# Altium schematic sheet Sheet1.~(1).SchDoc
size D; SheetNumber: 1; SheetTotal: 1
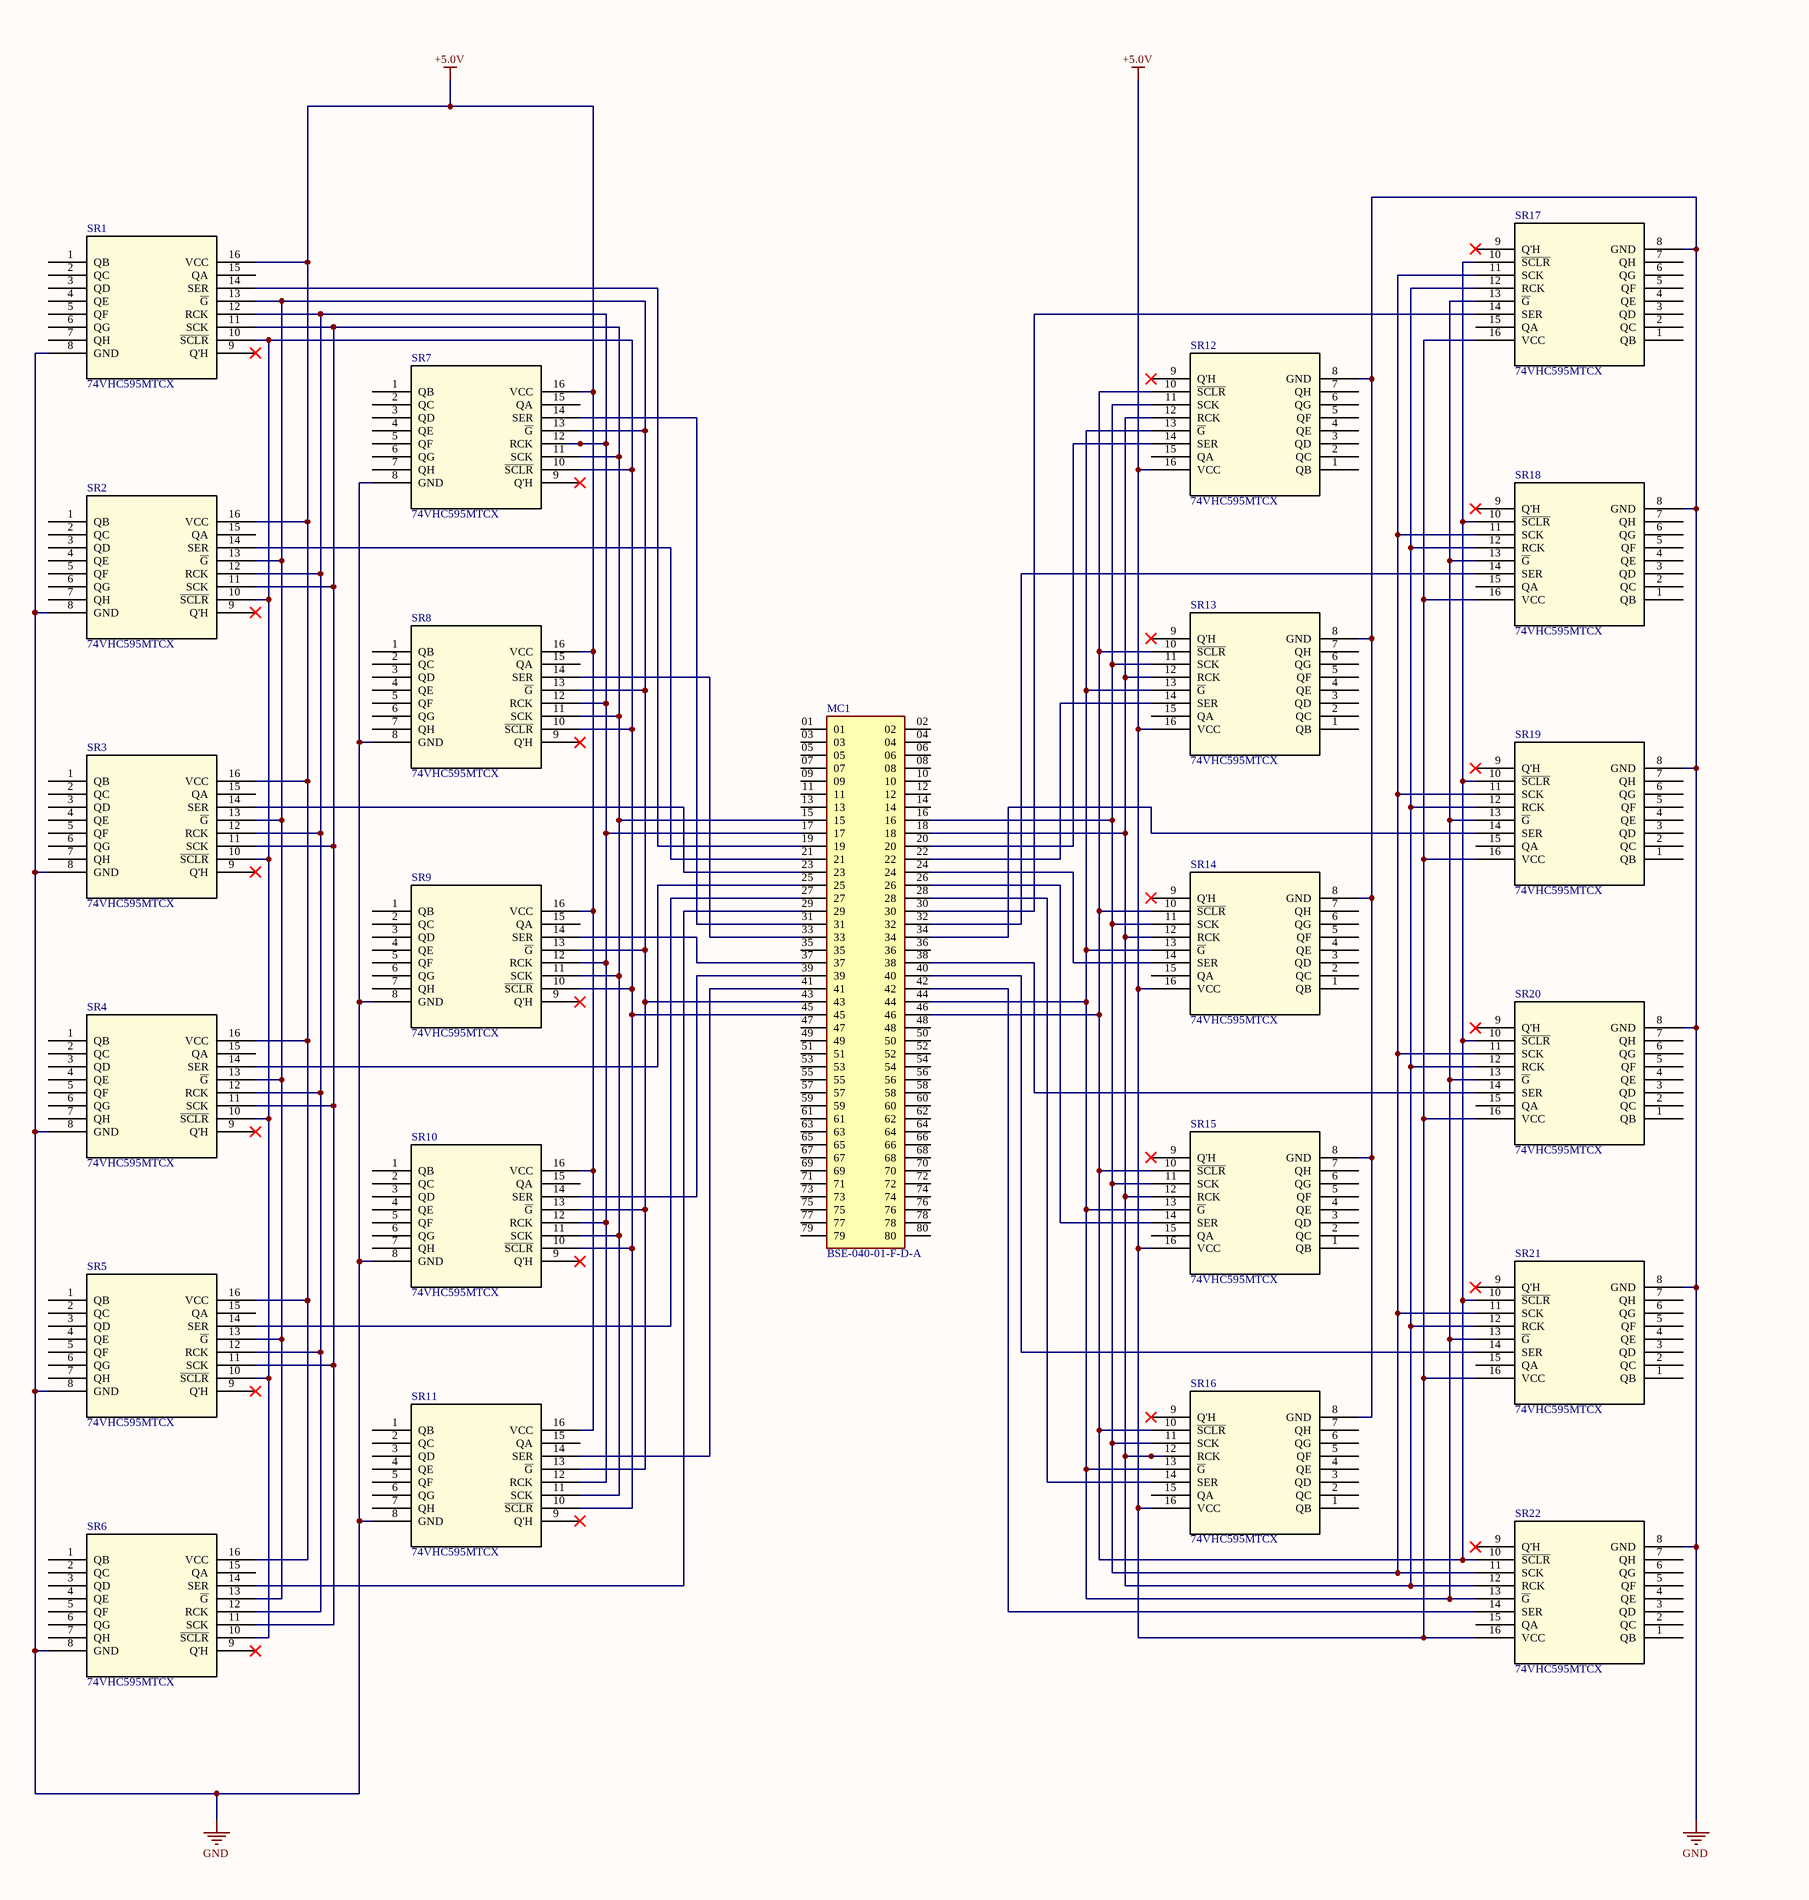
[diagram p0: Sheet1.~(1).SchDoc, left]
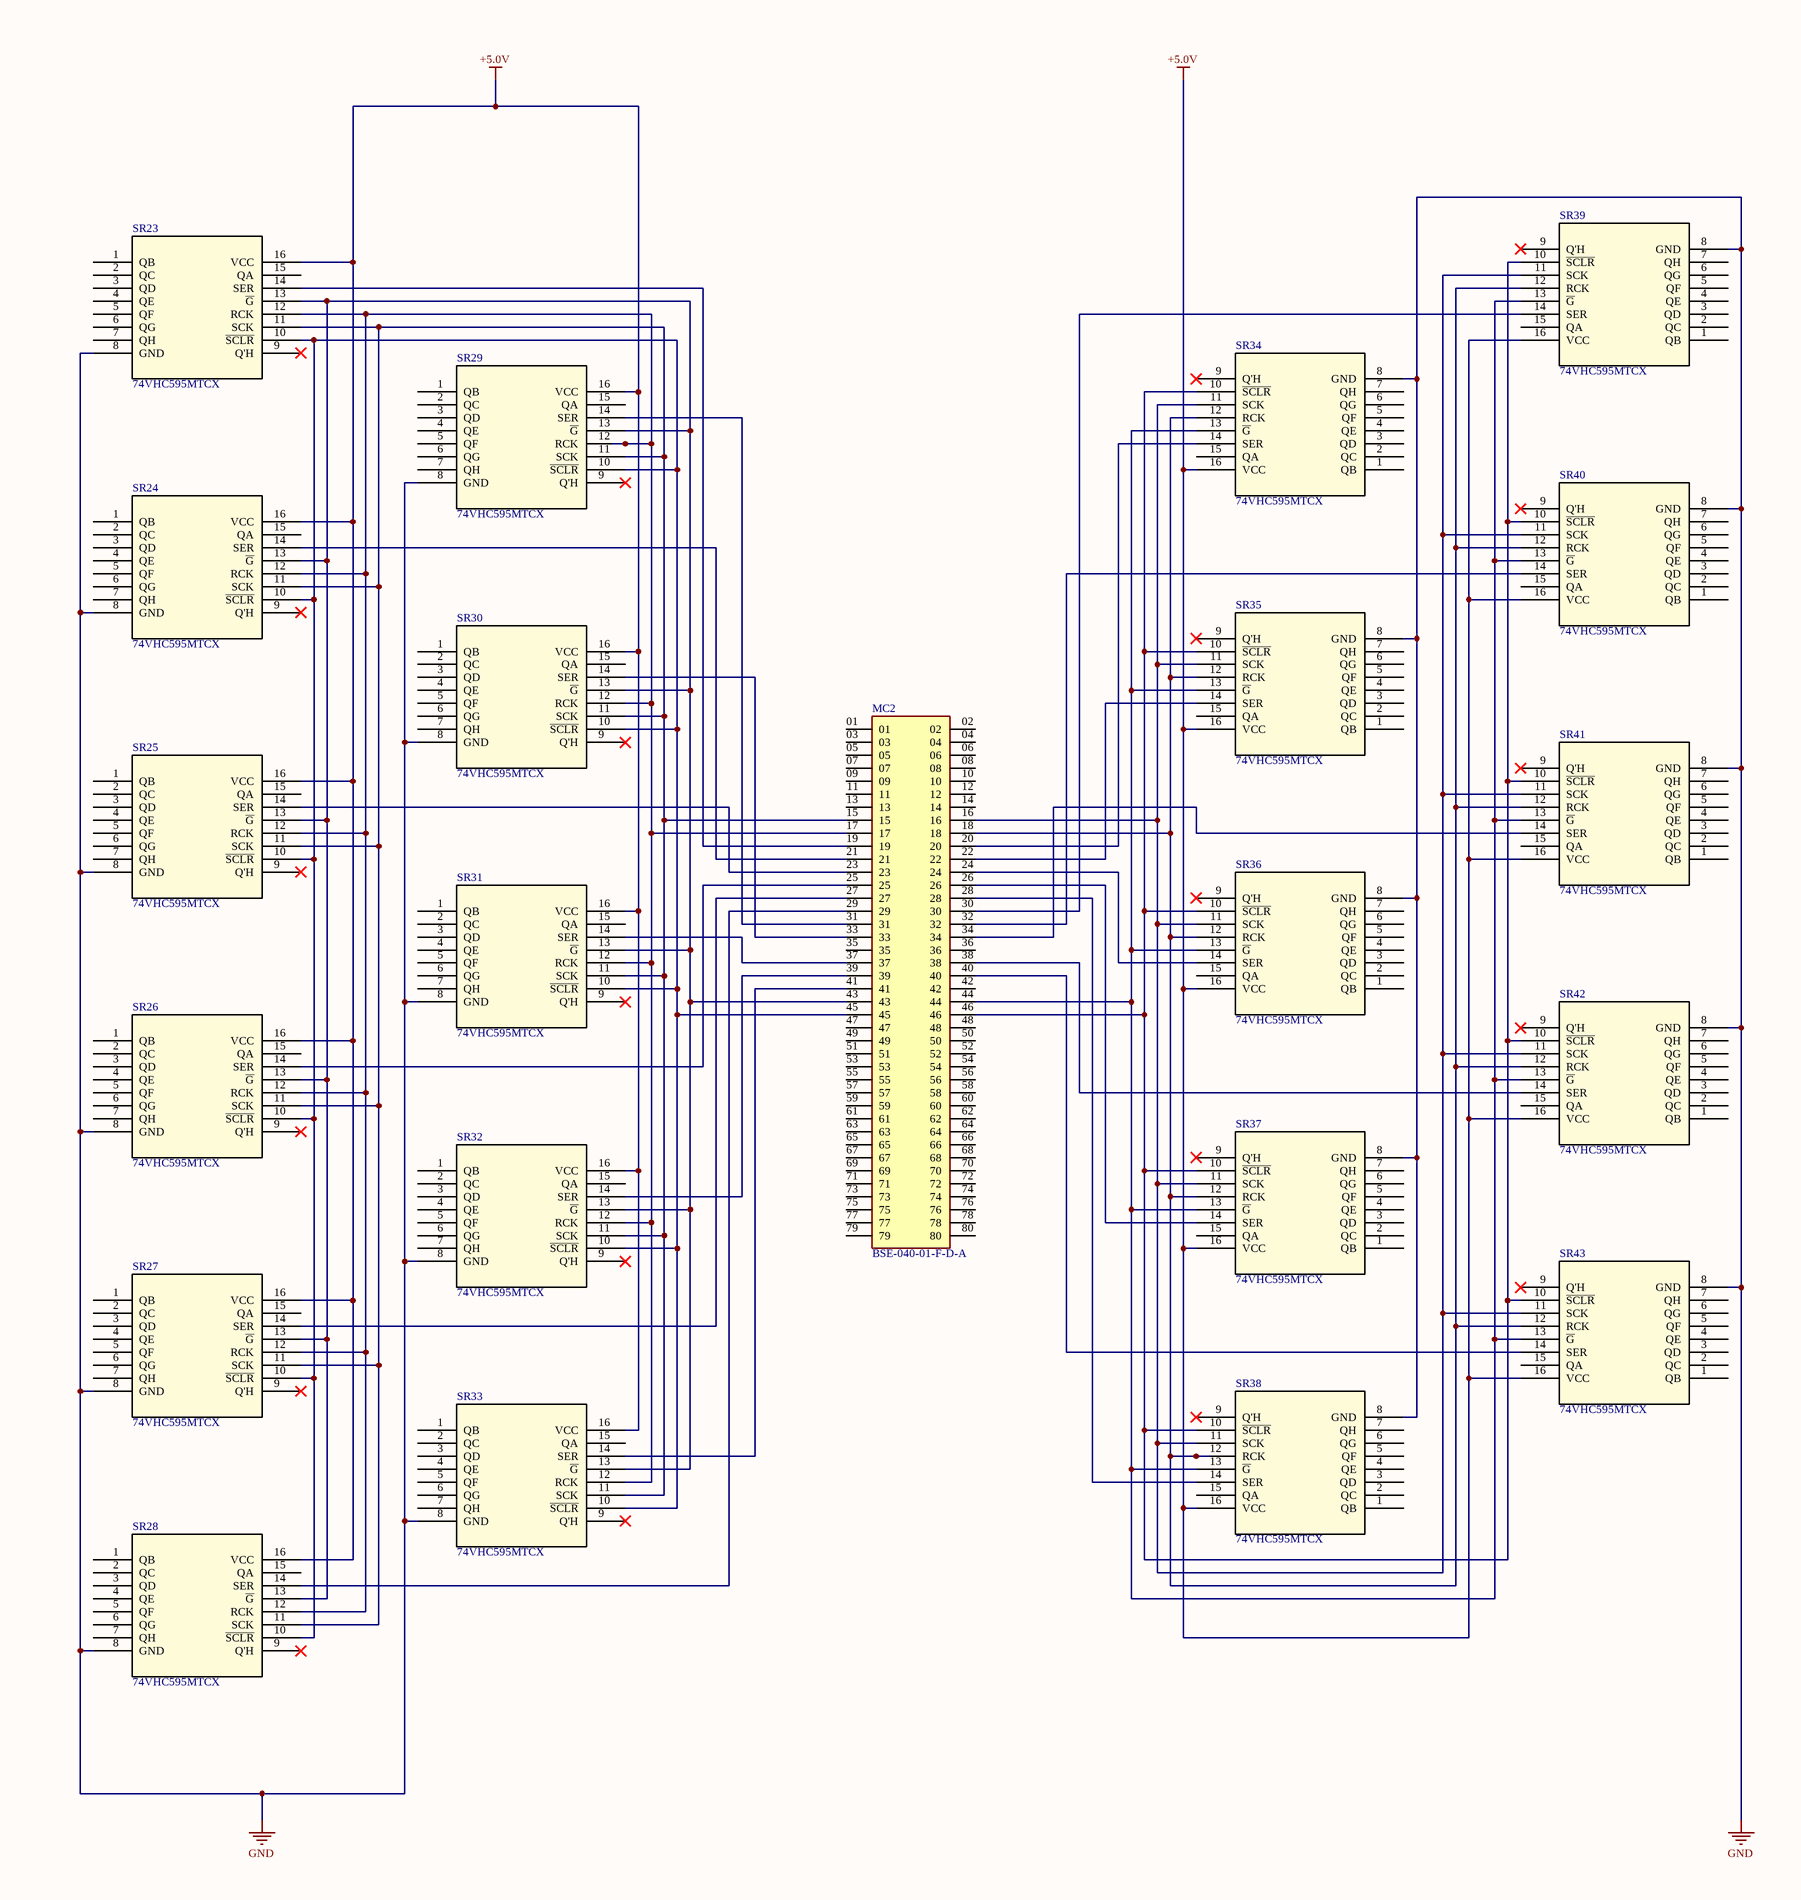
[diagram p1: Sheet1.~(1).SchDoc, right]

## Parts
MC1  BSE-040-01-F-D-A  [SAMTEC_BSE-040-01-X-D-A]
MC2  BSE-040-01-F-D-A  [SAMTEC_BSE-040-01-X-D-A]
SR1  74VHC595MTCX  [TSSOP16_5X4P5_ONS]
SR2  74VHC595MTCX  [TSSOP16_5X4P5_ONS]
SR3  74VHC595MTCX  [TSSOP16_5X4P5_ONS]
SR4  74VHC595MTCX  [TSSOP16_5X4P5_ONS]
SR5  74VHC595MTCX  [TSSOP16_5X4P5_ONS]
SR6  74VHC595MTCX  [TSSOP16_5X4P5_ONS]
SR7  74VHC595MTCX  [TSSOP16_5X4P5_ONS]
SR8  74VHC595MTCX  [TSSOP16_5X4P5_ONS]
SR9  74VHC595MTCX  [TSSOP16_5X4P5_ONS]
SR10  74VHC595MTCX  [TSSOP16_5X4P5_ONS]
SR11  74VHC595MTCX  [TSSOP16_5X4P5_ONS]
SR12  74VHC595MTCX  [TSSOP16_5X4P5_ONS]
SR13  74VHC595MTCX  [TSSOP16_5X4P5_ONS]
SR14  74VHC595MTCX  [TSSOP16_5X4P5_ONS]
SR15  74VHC595MTCX  [TSSOP16_5X4P5_ONS]
SR16  74VHC595MTCX  [TSSOP16_5X4P5_ONS]
SR17  74VHC595MTCX  [TSSOP16_5X4P5_ONS]
SR18  74VHC595MTCX  [TSSOP16_5X4P5_ONS]
SR19  74VHC595MTCX  [TSSOP16_5X4P5_ONS]
SR20  74VHC595MTCX  [TSSOP16_5X4P5_ONS]
SR21  74VHC595MTCX  [TSSOP16_5X4P5_ONS]
SR22  74VHC595MTCX  [TSSOP16_5X4P5_ONS]
SR23  74VHC595MTCX  [TSSOP16_5X4P5_ONS]
SR24  74VHC595MTCX  [TSSOP16_5X4P5_ONS]
SR25  74VHC595MTCX  [TSSOP16_5X4P5_ONS]
SR26  74VHC595MTCX  [TSSOP16_5X4P5_ONS]
SR27  74VHC595MTCX  [TSSOP16_5X4P5_ONS]
SR28  74VHC595MTCX  [TSSOP16_5X4P5_ONS]
SR29  74VHC595MTCX  [TSSOP16_5X4P5_ONS]
SR30  74VHC595MTCX  [TSSOP16_5X4P5_ONS]
SR31  74VHC595MTCX  [TSSOP16_5X4P5_ONS]
SR32  74VHC595MTCX  [TSSOP16_5X4P5_ONS]
SR33  74VHC595MTCX  [TSSOP16_5X4P5_ONS]
SR34  74VHC595MTCX  [TSSOP16_5X4P5_ONS]
SR35  74VHC595MTCX  [TSSOP16_5X4P5_ONS]
SR36  74VHC595MTCX  [TSSOP16_5X4P5_ONS]
SR37  74VHC595MTCX  [TSSOP16_5X4P5_ONS]
SR38  74VHC595MTCX  [TSSOP16_5X4P5_ONS]
SR39  74VHC595MTCX  [TSSOP16_5X4P5_ONS]
SR40  74VHC595MTCX  [TSSOP16_5X4P5_ONS]
SR41  74VHC595MTCX  [TSSOP16_5X4P5_ONS]
SR42  74VHC595MTCX  [TSSOP16_5X4P5_ONS]
SR43  74VHC595MTCX  [TSSOP16_5X4P5_ONS]

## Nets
+5.0V: SR1.16(VCC) SR2.16(VCC) SR3.16(VCC) SR4.16(VCC) SR5.16(VCC) SR6.16(VCC) SR7.16(VCC) SR8.16(VCC) SR9.16(VCC) SR10.16(VCC) SR11.16(VCC) SR12.16(VCC) SR13.16(VCC) SR14.16(VCC) SR15.16(VCC) SR16.16(VCC) SR17.16(VCC) SR18.16(VCC) SR19.16(VCC) SR20.16(VCC) SR21.16(VCC) SR22.16(VCC) SR23.16(VCC) SR24.16(VCC) SR25.16(VCC) SR26.16(VCC) SR27.16(VCC) SR28.16(VCC) SR29.16(VCC) SR30.16(VCC) SR31.16(VCC) SR32.16(VCC) SR33.16(VCC) SR34.16(VCC) SR35.16(VCC) SR36.16(VCC) SR37.16(VCC) SR38.16(VCC) SR39.16(VCC) SR40.16(VCC) SR41.16(VCC) SR42.16(VCC) SR43.16(VCC)
GND: SR1.8(GND) SR2.8(GND) SR3.8(GND) SR4.8(GND) SR5.8(GND) SR6.8(GND) SR7.8(GND) SR8.8(GND) SR9.8(GND) SR10.8(GND) SR11.8(GND) SR12.8(GND) SR13.8(GND) SR14.8(GND) SR15.8(GND) SR16.8(GND) SR17.8(GND) SR18.8(GND) SR19.8(GND) SR20.8(GND) SR21.8(GND) SR22.8(GND) SR23.8(GND) SR24.8(GND) SR25.8(GND) SR26.8(GND) SR27.8(GND) SR28.8(GND) SR29.8(GND) SR30.8(GND) SR31.8(GND) SR32.8(GND) SR33.8(GND) SR34.8(GND) SR35.8(GND) SR36.8(GND) SR37.8(GND) SR38.8(GND) SR39.8(GND) SR40.8(GND) SR41.8(GND) SR42.8(GND) SR43.8(GND)
NetMC1_15: MC1.15 SR1.11(SCK) SR2.11(SCK) SR3.11(SCK) SR4.11(SCK) SR5.11(SCK) SR6.11(SCK) SR7.11(SCK) SR8.11(SCK) SR9.11(SCK) SR10.11(SCK) SR11.11(SCK)
NetMC1_16: MC1.16 SR12.11(SCK) SR13.11(SCK) SR14.11(SCK) SR15.11(SCK) SR16.11(SCK) SR17.11(SCK) SR18.11(SCK) SR19.11(SCK) SR20.11(SCK) SR21.11(SCK) SR22.11(SCK)
NetMC1_17: MC1.17 SR1.12(RCK) SR2.12(RCK) SR3.12(RCK) SR4.12(RCK) SR5.12(RCK) SR6.12(RCK) SR7.12(RCK) SR8.12(RCK) SR9.12(RCK) SR10.12(RCK) SR11.12(RCK)
NetMC1_18: MC1.18 SR12.12(RCK) SR13.12(RCK) SR14.12(RCK) SR15.12(RCK) SR16.12(RCK) SR17.12(RCK) SR18.12(RCK) SR19.12(RCK) SR20.12(RCK) SR21.12(RCK) SR22.12(RCK)
NetMC1_19: MC1.19 SR1.14(SER)
NetMC1_20: MC1.20 SR12.14(SER)
NetMC1_21: MC1.21 SR2.14(SER)
NetMC1_22: MC1.22 SR13.14(SER)
NetMC1_23: MC1.23 SR3.14(SER)
NetMC1_24: MC1.24 SR14.14(SER)
NetMC1_25: MC1.25 SR4.14(SER)
NetMC1_26: MC1.26 SR15.14(SER)
NetMC1_27: MC1.27 SR5.14(SER)
NetMC1_28: MC1.28 SR16.14(SER)
NetMC1_29: MC1.29 SR6.14(SER)
NetMC1_30: MC1.30 SR17.14(SER)
NetMC1_31: MC1.31 SR7.14(SER)
NetMC1_32: MC1.32 SR18.14(SER)
NetMC1_33: MC1.33 SR8.14(SER)
NetMC1_34: MC1.34 SR19.14(SER)
NetMC1_37: MC1.37 SR9.14(SER)
NetMC1_38: MC1.38 SR20.14(SER)
NetMC1_39: MC1.39 SR10.14(SER)
NetMC1_40: MC1.40 SR21.14(SER)
NetMC1_41: MC1.41 SR11.14(SER)
NetMC1_42: MC1.42 SR22.14(SER)
NetMC1_43: MC1.43 SR1.13(~{G}) SR2.13(~{G}) SR3.13(~{G}) SR4.13(~{G}) SR5.13(~{G}) SR6.13(~{G}) SR7.13(~{G}) SR8.13(~{G}) SR9.13(~{G}) SR10.13(~{G}) SR11.13(~{G})
NetMC1_44: MC1.44 SR12.13(~{G}) SR13.13(~{G}) SR14.13(~{G}) SR15.13(~{G}) SR16.13(~{G}) SR17.13(~{G}) SR18.13(~{G}) SR19.13(~{G}) SR20.13(~{G}) SR21.13(~{G}) SR22.13(~{G})
NetMC1_45: MC1.45 SR1.10(~{SCLR}) SR2.10(~{SCLR}) SR3.10(~{SCLR}) SR4.10(~{SCLR}) SR5.10(~{SCLR}) SR6.10(~{SCLR}) SR7.10(~{SCLR}) SR8.10(~{SCLR}) SR9.10(~{SCLR}) SR10.10(~{SCLR}) SR11.10(~{SCLR})
NetMC1_46: MC1.46 SR12.10(~{SCLR}) SR13.10(~{SCLR}) SR14.10(~{SCLR}) SR15.10(~{SCLR}) SR16.10(~{SCLR}) SR17.10(~{SCLR}) SR18.10(~{SCLR}) SR19.10(~{SCLR}) SR20.10(~{SCLR}) SR21.10(~{SCLR}) SR22.10(~{SCLR})
NetMC2_15: MC2.15 SR23.11(SCK) SR24.11(SCK) SR25.11(SCK) SR26.11(SCK) SR27.11(SCK) SR28.11(SCK) SR29.11(SCK) SR30.11(SCK) SR31.11(SCK) SR32.11(SCK) SR33.11(SCK)
NetMC2_16: MC2.16 SR34.11(SCK) SR35.11(SCK) SR36.11(SCK) SR37.11(SCK) SR38.11(SCK) SR39.11(SCK) SR40.11(SCK) SR41.11(SCK) SR42.11(SCK) SR43.11(SCK)
NetMC2_17: MC2.17 SR23.12(RCK) SR24.12(RCK) SR25.12(RCK) SR26.12(RCK) SR27.12(RCK) SR28.12(RCK) SR29.12(RCK) SR30.12(RCK) SR31.12(RCK) SR32.12(RCK) SR33.12(RCK)
NetMC2_18: MC2.18 SR34.12(RCK) SR35.12(RCK) SR36.12(RCK) SR37.12(RCK) SR38.12(RCK) SR39.12(RCK) SR40.12(RCK) SR41.12(RCK) SR42.12(RCK) SR43.12(RCK)
NetMC2_19: MC2.19 SR23.14(SER)
NetMC2_20: MC2.20 SR34.14(SER)
NetMC2_21: MC2.21 SR24.14(SER)
NetMC2_22: MC2.22 SR35.14(SER)
NetMC2_23: MC2.23 SR25.14(SER)
NetMC2_24: MC2.24 SR36.14(SER)
NetMC2_25: MC2.25 SR26.14(SER)
NetMC2_26: MC2.26 SR37.14(SER)
NetMC2_27: MC2.27 SR27.14(SER)
NetMC2_28: MC2.28 SR38.14(SER)
NetMC2_29: MC2.29 SR28.14(SER)
NetMC2_30: MC2.30 SR39.14(SER)
NetMC2_31: MC2.31 SR29.14(SER)
NetMC2_32: MC2.32 SR40.14(SER)
NetMC2_33: MC2.33 SR30.14(SER)
NetMC2_34: MC2.34 SR41.14(SER)
NetMC2_37: MC2.37 SR31.14(SER)
NetMC2_38: MC2.38 SR42.14(SER)
NetMC2_39: MC2.39 SR32.14(SER)
NetMC2_40: MC2.40 SR43.14(SER)
NetMC2_41: MC2.41 SR33.14(SER)
NetMC2_43: MC2.43 SR23.13(~{G}) SR24.13(~{G}) SR25.13(~{G}) SR26.13(~{G}) SR27.13(~{G}) SR28.13(~{G}) SR29.13(~{G}) SR30.13(~{G}) SR31.13(~{G}) SR32.13(~{G}) SR33.13(~{G})
NetMC2_44: MC2.44 SR34.13(~{G}) SR35.13(~{G}) SR36.13(~{G}) SR37.13(~{G}) SR38.13(~{G}) SR39.13(~{G}) SR40.13(~{G}) SR41.13(~{G}) SR42.13(~{G}) SR43.13(~{G})
NetMC2_45: MC2.45 SR23.10(~{SCLR}) SR24.10(~{SCLR}) SR25.10(~{SCLR}) SR26.10(~{SCLR}) SR27.10(~{SCLR}) SR28.10(~{SCLR}) SR29.10(~{SCLR}) SR30.10(~{SCLR}) SR31.10(~{SCLR}) SR32.10(~{SCLR}) SR33.10(~{SCLR})
NetMC2_46: MC2.46 SR34.10(~{SCLR}) SR35.10(~{SCLR}) SR36.10(~{SCLR}) SR37.10(~{SCLR}) SR38.10(~{SCLR}) SR39.10(~{SCLR}) SR40.10(~{SCLR}) SR41.10(~{SCLR}) SR42.10(~{SCLR}) SR43.10(~{SCLR})

Not connected (* = marked no-connect by the designer): MC1 01 02 03 04 05 06 07 08 09 10 11 12 13 14 35 36 47 48 49 50 51 52 53 54 55 56 57 58 59 60 61 62 63 64 65 66 67 68 69 70 71 72 73 74 75 76 77 78 79 80; MC2 01 02 03 04 05 06 07 08 09 10 11 12 13 14 35 36 42 47 48 49 50 51 52 53 54 55 56 57 58 59 60 61 62 63 64 65 66 67 68 69 70 71 72 73 74 75 76 77 78 79 80; SR1 1(QB) 2(QC) 3(QD) 4(QE) 5(QF) 6(QG) 7(QH) 9(Q'H)* 15(QA); SR2 1(QB) 2(QC) 3(QD) 4(QE) 5(QF) 6(QG) 7(QH) 9(Q'H)* 15(QA); SR3 1(QB) 2(QC) 3(QD) 4(QE) 5(QF) 6(QG) 7(QH) 9(Q'H)* 15(QA); SR4 1(QB) 2(QC) 3(QD) 4(QE) 5(QF) 6(QG) 7(QH) 9(Q'H)* 15(QA); SR5 1(QB) 2(QC) 3(QD) 4(QE) 5(QF) 6(QG) 7(QH) 9(Q'H)* 15(QA); SR6 1(QB) 2(QC) 3(QD) 4(QE) 5(QF) 6(QG) 7(QH) 9(Q'H)* 15(QA); SR7 1(QB) 2(QC) 3(QD) 4(QE) 5(QF) 6(QG) 7(QH) 9(Q'H)* 15(QA); SR8 1(QB) 2(QC) 3(QD) 4(QE) 5(QF) 6(QG) 7(QH) 9(Q'H)* 15(QA); SR9 1(QB) 2(QC) 3(QD) 4(QE) 5(QF) 6(QG) 7(QH) 9(Q'H)* 15(QA); SR10 1(QB) 2(QC) 3(QD) 4(QE) 5(QF) 6(QG) 7(QH) 9(Q'H)* 15(QA); SR11 1(QB) 2(QC) 3(QD) 4(QE) 5(QF) 6(QG) 7(QH) 9(Q'H)* 15(QA); SR12 1(QB) 2(QC) 3(QD) 4(QE) 5(QF) 6(QG) 7(QH) 9(Q'H)* 15(QA); SR13 1(QB) 2(QC) 3(QD) 4(QE) 5(QF) 6(QG) 7(QH) 9(Q'H)* 15(QA); SR14 1(QB) 2(QC) 3(QD) 4(QE) 5(QF) 6(QG) 7(QH) 9(Q'H)* 15(QA); SR15 1(QB) 2(QC) 3(QD) 4(QE) 5(QF) 6(QG) 7(QH) 9(Q'H)* 15(QA); SR16 1(QB) 2(QC) 3(QD) 4(QE) 5(QF) 6(QG) 7(QH) 9(Q'H)* 15(QA); SR17 1(QB) 2(QC) 3(QD) 4(QE) 5(QF) 6(QG) 7(QH) 9(Q'H)* 15(QA); SR18 1(QB) 2(QC) 3(QD) 4(QE) 5(QF) 6(QG) 7(QH) 9(Q'H)* 15(QA); SR19 1(QB) 2(QC) 3(QD) 4(QE) 5(QF) 6(QG) 7(QH) 9(Q'H)* 15(QA); SR20 1(QB) 2(QC) 3(QD) 4(QE) 5(QF) 6(QG) 7(QH) 9(Q'H)* 15(QA); SR21 1(QB) 2(QC) 3(QD) 4(QE) 5(QF) 6(QG) 7(QH) 9(Q'H)* 15(QA); SR22 1(QB) 2(QC) 3(QD) 4(QE) 5(QF) 6(QG) 7(QH) 9(Q'H)* 15(QA); SR23 1(QB) 2(QC) 3(QD) 4(QE) 5(QF) 6(QG) 7(QH) 9(Q'H)* 15(QA); SR24 1(QB) 2(QC) 3(QD) 4(QE) 5(QF) 6(QG) 7(QH) 9(Q'H)* 15(QA); SR25 1(QB) 2(QC) 3(QD) 4(QE) 5(QF) 6(QG) 7(QH) 9(Q'H)* 15(QA); SR26 1(QB) 2(QC) 3(QD) 4(QE) 5(QF) 6(QG) 7(QH) 9(Q'H)* 15(QA); SR27 1(QB) 2(QC) 3(QD) 4(QE) 5(QF) 6(QG) 7(QH) 9(Q'H)* 15(QA); SR28 1(QB) 2(QC) 3(QD) 4(QE) 5(QF) 6(QG) 7(QH) 9(Q'H)* 15(QA); SR29 1(QB) 2(QC) 3(QD) 4(QE) 5(QF) 6(QG) 7(QH) 9(Q'H)* 15(QA); SR30 1(QB) 2(QC) 3(QD) 4(QE) 5(QF) 6(QG) 7(QH) 9(Q'H)* 15(QA); SR31 1(QB) 2(QC) 3(QD) 4(QE) 5(QF) 6(QG) 7(QH) 9(Q'H)* 15(QA); SR32 1(QB) 2(QC) 3(QD) 4(QE) 5(QF) 6(QG) 7(QH) 9(Q'H)* 15(QA); SR33 1(QB) 2(QC) 3(QD) 4(QE) 5(QF) 6(QG) 7(QH) 9(Q'H)* 15(QA); SR34 1(QB) 2(QC) 3(QD) 4(QE) 5(QF) 6(QG) 7(QH) 9(Q'H)* 15(QA); SR35 1(QB) 2(QC) 3(QD) 4(QE) 5(QF) 6(QG) 7(QH) 9(Q'H)* 15(QA); SR36 1(QB) 2(QC) 3(QD) 4(QE) 5(QF) 6(QG) 7(QH) 9(Q'H)* 15(QA); SR37 1(QB) 2(QC) 3(QD) 4(QE) 5(QF) 6(QG) 7(QH) 9(Q'H)* 15(QA); SR38 1(QB) 2(QC) 3(QD) 4(QE) 5(QF) 6(QG) 7(QH) 9(Q'H)* 15(QA); SR39 1(QB) 2(QC) 3(QD) 4(QE) 5(QF) 6(QG) 7(QH) 9(Q'H)* 15(QA); SR40 1(QB) 2(QC) 3(QD) 4(QE) 5(QF) 6(QG) 7(QH) 9(Q'H)* 15(QA); SR41 1(QB) 2(QC) 3(QD) 4(QE) 5(QF) 6(QG) 7(QH) 9(Q'H)* 15(QA); SR42 1(QB) 2(QC) 3(QD) 4(QE) 5(QF) 6(QG) 7(QH) 9(Q'H)* 15(QA); SR43 1(QB) 2(QC) 3(QD) 4(QE) 5(QF) 6(QG) 7(QH) 9(Q'H)* 15(QA)

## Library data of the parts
MC1 MC2 = BSE-040-01-X-D-A: 0.80 mm Basic Blade & Beam Socket Strip
SR1-SR43 = 74VHC595MTCX: No Description Available; Mfr_Name: onsemi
